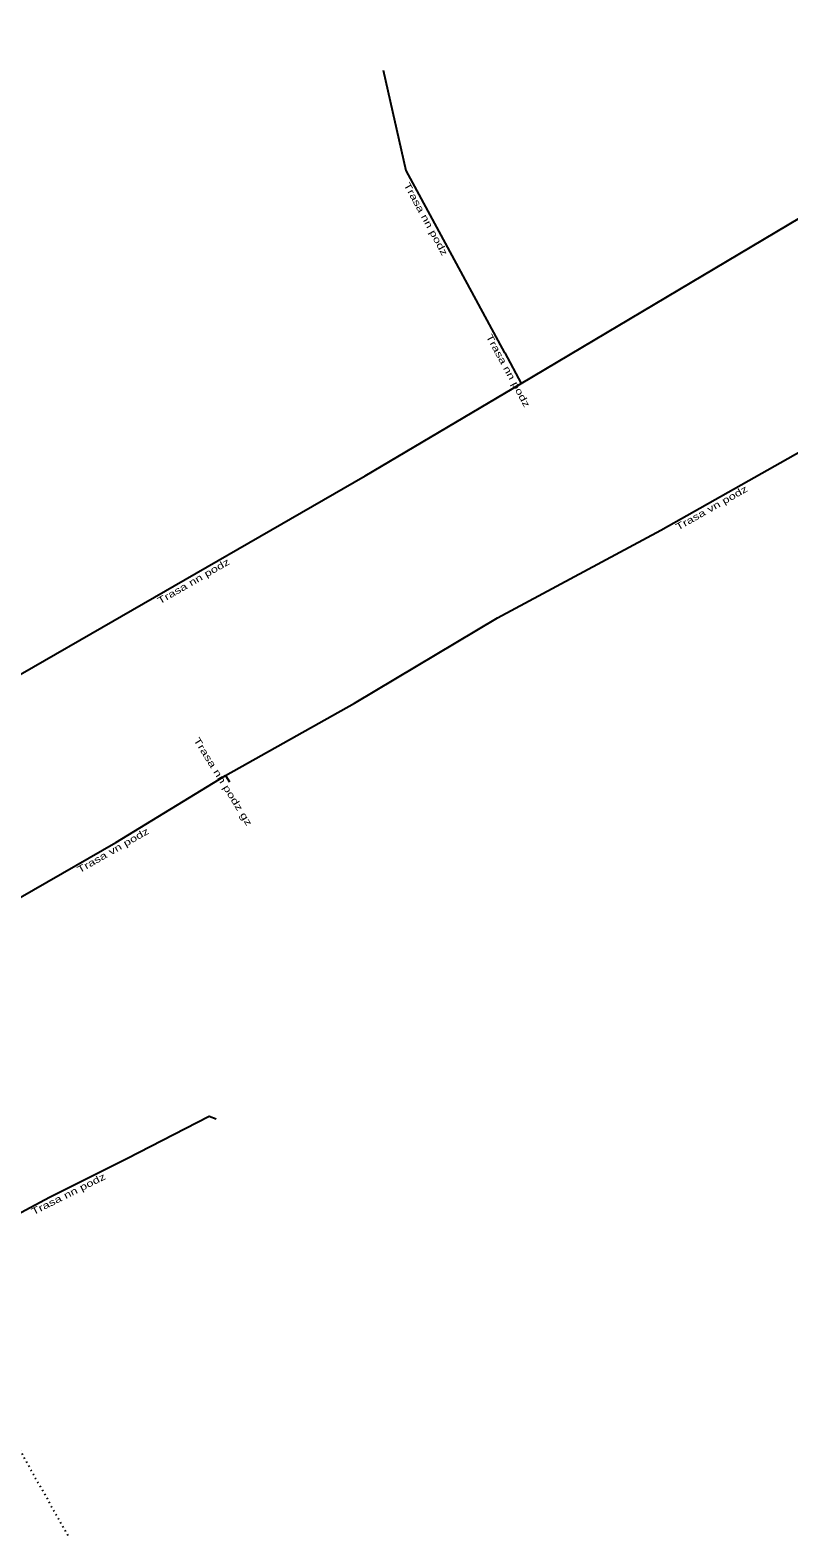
# Model space of a CAD drawing. Extents: x -733620 to -732615, y -1025255 to -1024617.
# Drawn here: x -733317.4 to -733261.7, y -1025014.4 to -1024903.7 of the extents above; entities that cross this region are included whole.
import ezdxf
from ezdxf.enums import TextEntityAlignment as Align

# ---------------------------------------------------------------- set-up
doc = ezdxf.new("R2010")
doc.units = 0
doc.header["$LTSCALE"] = 0.2
doc.linetypes.add('DOTTED', pattern=[1.5, 0.3, -1.2])
doc.linetypes.add('MEDIUM_DASHED', pattern=[4.5, 3, -1.5])
doc.layers.add('11', color=7, linetype='MEDIUM_DASHED', lineweight=25)
doc.layers.add('21', color=7, linetype='Continuous', lineweight=25)
doc.layers.add('20', color=7, linetype='Continuous')

msp = doc.modelspace()

# ---------------------------------------------------------------- linework, layer by layer
at = {"layer": '11', "linetype": 'Continuous'}
msp.add_line((-733303.01, -1024958.431), (-733302.72, -1024958.9), dxfattribs=at)
at = {"layer": '11', "linetype": 'DOTTED'}
msp.add_line((-733325.654, -1024994.581), (-733314.5, -1025014.4), dxfattribs=at)
at = {"layer": '11', "linetype": 'Continuous'}
for points in [[(-733281.31, -1024929.64), (-733260.86, -1024917.5), (-733241.06, -1024906.39), (-733223.38, -1024896.65), (-733210.88, -1024889.72)], [(-733291.44, -1024906.64), (-733289.78, -1024914.02), (-733282.527, -1024927.395)], [(-733282.527, -1024927.395), (-733282.52, -1024927.408), (-733281.31, -1024929.64)], [(-733329.94, -1024957.81), (-733312.9, -1024948.04), (-733292.77, -1024936.44), (-733281.31, -1024929.64)], [(-733325.654, -1024994.581), (-733315.935, -1024989.398), (-733310.255, -1024986.557), (-733304.214, -1024983.438), (-733303.703, -1024983.642)]]:
    msp.add_lwpolyline(points, dxfattribs=at)
at = {"layer": '21'}
for points in [[(-733303.01, -1024958.431), (-733293.549, -1024953.112), (-733283.044, -1024946.856), (-733271.06, -1024940.421), (-733249.944, -1024928.499), (-733232.463, -1024918.841), (-733232.256, -1024918.604), (-733232.093, -1024918.419)], [(-733320.084, -1024968.504), (-733311.077, -1024963.344), (-733303.01, -1024958.431)]]:
    msp.add_lwpolyline(points, dxfattribs=at)

# ---------------------------------------------------------------- texts
at = {"layer": '20'}
for s, rotation, width, p in [('Trasa nn podz', 298.469, 1.4, (-733288.5276, -1024917.6913)), ('Trasa nn podz', 298.47, 1.4, (-733282.4895, -1024928.8263)), ('Trasa vn podz', 29.449, 1.4, (-733267.2134, -1024938.9954)), ('Trasa nn podz', 29.953, 1.4, (-733305.2463, -1024944.3795)), ('Trasa nn podz gz', 301.761, 1.45, (-733303.4164, -1024959.0079)), ('Trasa vn podz', 29.81, 1.4, (-733311.1598, -1024964.1395)), ('Trasa nn podz', 26.573, 1.4, (-733314.4433, -1024989.3777))]:
    msp.add_text(s, height=0.5, rotation=rotation, dxfattribs=dict(at, width=width)).set_placement(p, align=Align.CENTER)

doc.saveas('drawing.dxf')
